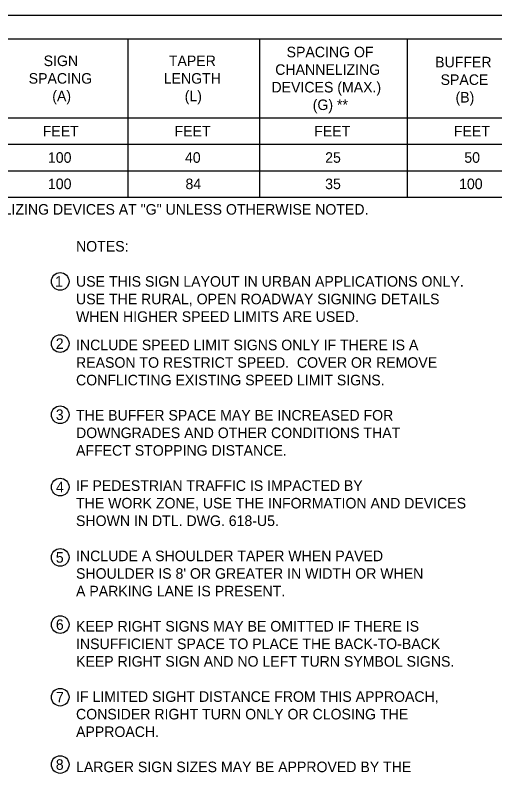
# Model space of a CAD drawing. Extents: x 49991.4 to 50021, y 49987.6 to 50011.4.
# Drawn here: x 50004.689 to 50007.418, y 49994.657 to 49998.999 of the extents above; entities that cross this region are included whole.
import ezdxf

# ---------------------------------------------------------------- set-up
doc = ezdxf.new("R2010")
doc.units = 0
doc.layers.add('Level 1', color=7, linetype='Continuous')
doc.layers.add('Level 2', color=7, linetype='Continuous')

msp = doc.modelspace()

# ---------------------------------------------------------------- linework, layer by layer
at = {"layer": 'Level 1'}
msp.add_lwpolyline([(49999.3835, 49998.9992), (50016.7501, 49998.9992), (50016.7501, 49987.7988), (49999.3835, 49987.7988)], close=True, dxfattribs=at)
at = {"layer": 'Level 2'}
for p, q in [((50003.7395, 49998.8652), (50007.6695, 49998.8652)), ((50005.3295, 49998.8652), (50005.3295, 49997.9652)), ((50006.0795, 49998.8652), (50006.0795, 49997.9652)), ((50006.9195, 49998.8652), (50006.9195, 49997.9652)), ((50003.7395, 49998.4152), (50007.6695, 49998.4152)), ((50003.7395, 49998.2652), (50007.6695, 49998.2652)), ((50003.7395, 49998.1152), (50007.6695, 49998.1152)), ((50003.7395, 49997.9652), (50007.6695, 49997.9652))]:
    msp.add_line(p, q, dxfattribs=at)
for centre in [(50004.9444, 49997.4853), (50004.9444, 49997.1317), (50004.9444, 49996.7272), (50004.9444, 49996.3158), (50004.9444, 49995.9155), (50004.9444, 49995.5333), (50004.9444, 49995.1205), (50004.9444, 49994.7374)]:
    msp.add_circle(centre, 0.0501, dxfattribs=at)

# ---------------------------------------------------------------- texts
for s, p in [('SPACING OF', (50006.233, 49998.7602)), ('SIGN', (50004.8502, 49998.7102)), ('TAPER', (50005.5628, 49998.7102)), ('BUFFER', (50007.0785, 49998.7029)), ('CHANNELIZING', (50006.1683, 49998.6602)), ('SPACING', (50004.7651, 49998.6102)), ('LENGTH', (50005.5337, 49998.6102)), ('SPACE', (50007.1093, 49998.6029)), ('DEVICES (MAX.)', (50006.1469, 49998.5602)), ('(A)', (50004.8992, 49998.5102)), ('(L)', (50005.6529, 49998.5102)), ('(B)', (50007.1944, 49998.5029)), ('(G) **', (50006.3816, 49998.4602)), ('FEET', (50004.8449, 49998.3102)), ('FEET', (50005.5949, 49998.3102)), ('FEET', (50006.3899, 49998.3102)), ('FEET', (50007.1849, 49998.3102)), ('100', (50004.8746, 49998.1602)), ('40', (50005.6546, 49998.1602)), ('25', (50006.4525, 49998.1602)), ('50', (50007.2445, 49998.1602)), ('100', (50004.8746, 49998.0102)), ('84', (50005.6575, 49998.0102)), ('35', (50006.4525, 49998.0102)), ('100', (50007.2146, 49998.0102)), ('** SPACE ALL CHANNELIZING DEVICES AT "G" UNLESS OTHERWISE NOTED.', (50003.7395, 49997.8652)), ('NOTES:', (50005.0345, 49997.6553)), ('1', (50004.915, 49997.4554)), ('USE THIS SIGN LAYOUT IN URBAN APPLICATIONS ONLY. ', (50005.0345, 49997.4553)), ('USE THE RURAL, OPEN ROADWAY SIGNING DETAILS ', (50005.0345, 49997.3553)), ('WHEN HIGHER SPEED LIMITS ARE USED.', (50005.0345, 49997.2553)), ('2', (50004.9192, 49997.1017)), ('INCLUDE SPEED LIMIT SIGNS ONLY IF THERE IS A', (50005.0345, 49997.0941)), ('REASON TO RESTRICT SPEED.  COVER OR REMOVE', (50005.0345, 49996.9941)), ('CONFLICTING EXISTING SPEED LIMIT SIGNS.', (50005.0345, 49996.8941)), ('3', (50004.9192, 49996.6972)), ('THE BUFFER SPACE MAY BE INCREASED FOR', (50005.0345, 49996.6941)), ('DOWNGRADES AND OTHER CONDITIONS THAT', (50005.0345, 49996.5941)), ('AFFECT STOPPING DISTANCE.', (50005.0345, 49996.4941)), ('4', (50004.9204, 49996.2858)), ('IF PEDESTRIAN TRAFFIC IS IMPACTED BY', (50005.0345, 49996.2941)), ('THE WORK ZONE, USE THE INFORMATION AND DEVICES ', (50005.0345, 49996.1941)), ('SHOWN IN DTL. DWG. 618-U5.', (50005.0345, 49996.0941)), ('INCLUDE A SHOULDER TAPER WHEN PAVED', (50005.0345, 49995.8941)), ('5', (50004.9195, 49995.8855)), ("SHOULDER IS 8' OR GREATER IN WIDTH OR WHEN ", (50005.0345, 49995.7941)), ('A PARKING LANE IS PRESENT.', (50005.0345, 49995.6941)), ('6', (50004.9198, 49995.5033)), ('KEEP RIGHT SIGNS MAY BE OMITTED IF THERE IS', (50005.0345, 49995.4941)), ('INSUFFICIENT SPACE TO PLACE THE BACK-TO-BACK', (50005.0345, 49995.3941)), ('KEEP RIGHT SIGN AND NO LEFT TURN SYMBOL SIGNS.', (50005.0345, 49995.2941)), ('7', (50004.9206, 49995.0905)), ('IF LIMITED SIGHT DISTANCE FROM THIS APPROACH,', (50005.0345, 49995.0941)), ('CONSIDER RIGHT TURN ONLY OR CLOSING THE ', (50005.0345, 49994.9941)), ('APPROACH.', (50005.0345, 49994.8941)), ('8', (50004.9194, 49994.7074)), ('LARGER SIGN SIZES MAY BE APPROVED BY THE ', (50005.0345, 49994.6941))]:
    msp.add_text(s, height=0.06, dxfattribs=at).set_placement(p)

doc.saveas('drawing.dxf')
